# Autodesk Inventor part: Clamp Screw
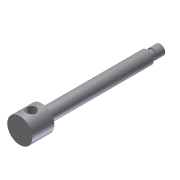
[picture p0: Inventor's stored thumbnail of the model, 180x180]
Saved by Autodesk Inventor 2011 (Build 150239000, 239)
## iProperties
Shininess: 77.0
Length Units: 11269
Angle Units: 11279
Time Units: 11290
Mass Units: 11283
Length Display Precision: 3
Angle Display Precision: 2
Created: 2002-02
Part Number: Clamp Screw
Document SubType Name: Modeling
Designer: ***
Density: 1 g/cm^3
Mass: 23.444 g
Surface Area: 81.4202 cm^2
Volume: 23.444 cm^3
Density: 0.0
Volumn: 0.0
Area: 0.0
PropertySet Name: Model Information
Control State: 0
Master: False
Checked Out: False
Author: ***
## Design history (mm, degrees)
sketch "Sketch1"
  geometry: L1 (0, 140)-(5, 140); L2 (5, 140)-(5, 132); L3 (5, 132)-(4, 132); L4 (4, 132)-(4, 127); L5 (4, 127)-(6.5, 127); L6 (6.5, 127)-(6.5, 25); L7 (6.5, 25)-(4, 25); L8 (4, 25)-(4, 22); L9 (4, 22)-(12.5, 22); L10 (12.5, 22)-(12.5, 0); L11 (12.5, 0)-(0, 0); L12 (0, 0)-(0, 140)
  constraints: 24 end point, 10 parallel, 1 horizontal, 1 perpendicular
  dimensions: "d0" = 10 diameter of L2 L12; "d1" = 8 diameter of L4 L12; "d2" = 13 diameter of L6 L12; "d3" = 8 diameter of L7.end L12; "d4" = 25 diameter of L10 L12; "d5" = 3 distance from line of L7.end L9; "d6" = 8 distance of L1.end L2.end; "d7" = 13 vertical distance of L1.end L5.end; "d8" = 22 distance of L9.end L10.end; "d10" = 102 distance of L5.end L6.end
revolve "Revolution1" sketch "Sketch1" stored, may be unused: angle "d11" = 90 deg
sketch "Sketch3"
  geometry: L1 (-12.5, 0)-(12.5, 0) reference; C1 r 5 at (-0.113, 11)
  constraints: 1 centre point
  dimensions: "d13" = 10 diameter of C1; "d14" = 11 distance from line of L1 C1.centre
extrude "Extrusion1" cut sketch "Sketch3" stored distance "d15" = 10; taper "d16" = 0 deg
body "Solid1"
